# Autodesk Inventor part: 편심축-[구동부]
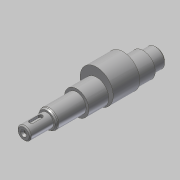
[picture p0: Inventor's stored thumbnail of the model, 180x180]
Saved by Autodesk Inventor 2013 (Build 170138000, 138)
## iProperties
Created: 2019-01
Part Number: 편심축-[구동부]
Material: 강철, 연강
Document SubType Name: Modeling
Designer: mduedu
Density: 7.86 g/cm^3
Mass: 326.79 g
Surface Area: 90.982 cm^2
Volume: 41.5764 cm^3
Author: mduedu
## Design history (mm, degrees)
sketch "스케치1"
  geometry: L1 (0, 0)-(21, 0); L2 (21, 0)-(21, 6); L3 (21, 6)-(0, 6); L4 (0, 6)-(0, 0); L5 (21, 0)-(48, 0); L6 (48, 0)-(48, 8.5); L7 (48, 8.5)-(21, 8.5); L8 (21, 8.5)-(21, 0); L9 (48, 0)-(108, 0); L10 (108, 0)-(108, 11); L11 (108, 11)-(48, 11); L12 (48, 11)-(48, 0); L13 (108, 0)-(120, 0); L14 (120, 0)-(120, 8.5); L15 (120, 8.5)-(108, 8.5); L16 (108, 8.5)-(108, 0)
  constraints: 32 end point, 8 parallel, 4 horizontal, 4 perpendicular
  dimensions: "d0" = 120 distance between parallel lines of L14 L4; "d2" = 12 distance of L14.end L15.end; "d3" = 60 distance of L10.end L11.end; "d4" = 99 distance between parallel lines of L8 L14; "d5" = 12 diameter of L3 L1; "d6" = 17 diameter of L7 L5; "d7" = 17 diameter of L15 L13; "d8" = 22 diameter of L11 L9
revolve "회전1" sketch "스케치1" stored, may be unused: angle "d9" = 90 deg
node "작업 평면1"
sketch "스케치2"
  geometry: C1 r 15 at (0, 4); C2 r 11 at (0, 0) reference; 1 further point
  constraints: 1 centre point, 1 tangent, 1 vertical alignment
  dimensions: "d11" = 4 distance of point (0, 0) C1.centre
extrude "돌출1" join sketch "스케치2" distance "d12" = 24; taper "d13" = 0 deg
node "작업 평면2"
sketch "스케치3" dims "d16" = 12
  geometry: L1 (-4.5, 2)-(3.5, 2); L2 (3.5, 2)-(3.5, -2); L3 (3.5, -2)-(-4.5, -2); L4 (-4.5, -2)-(-4.5, 2); L5 (-10.5, 8.5)-(-10.5, -8.5) reference; 3 further points
  constraints: 8 end point, 2 midpoint, 2 parallel, 2 vertical alignment, 1 horizontal, 1 horizontal alignment, 1 perpendicular, 4 other
  dimensions: "d14" = 4 distance between parallel lines of L3 L1; "d17" = 4 dimension on L5
extrude "돌출2" cut sketch "스케치3" distance "d18" = 2.5; taper "d19" = 0 deg
chamfer "모따기1" distance "d20" = 1.82; stored, may be unused: second distance "d21" = 2, angle "d22" = 30 deg
fillet "모깎기1" dims "d23" = 2
hole "구멍2" diameter "d39" = 3.242; stored, may be unused: countersink angle "d43" = 60 deg, drill point angle "d45" = 118 deg; dims "d37" = 10, "d38" = 10, "d40" = 8, "d41" = 5.51, "d42" = 2, "d44" = 10
sketch "스케치5"
  geometry: L1 (0, 0)-(2, 0); L2 (2, 0)-(2, 1.621); L3 (0, 2.776)-(0, 0); L4 (0, 2.776)-(2, 1.621); L5 (10, 1.621)-(0, 1.621) reference
  constraints: 8 end point, 1 horizontal, 1 parallel, 1 perpendicular, 1 point on line
  dimensions: "d46" = 2 distance between parallel lines of L2 L3; "d48" = 30 deg angle of L4 L1
revolve "회전2" sketch "스케치5" stored, may be unused: angle "d50" = 90 deg
chamfer "모따기2" distance "d25" = 1; stored, may be unused: second distance "d26" = 2, angle "d27" = 30 deg
node "솔리드1"
